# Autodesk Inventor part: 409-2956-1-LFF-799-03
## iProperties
Created: 2010-11
Part Number: 409-2956-1-LFF-799-03
Material: 3/4" OD TUBE - SS
Document SubType Name: Modeling
Designer: S. Boerckel
Engineer: Steve Boerckel
Mass: 309.983 g
Surface Area: 466.545 cm^2
Volume: 38.3643 cm^3
Density: 8.08 g/cm^3
Description: DRAIN TUBING
Length: 15.638 in
Author: S. Boerckel
Revision Number: 0
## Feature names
1. Sweep1
